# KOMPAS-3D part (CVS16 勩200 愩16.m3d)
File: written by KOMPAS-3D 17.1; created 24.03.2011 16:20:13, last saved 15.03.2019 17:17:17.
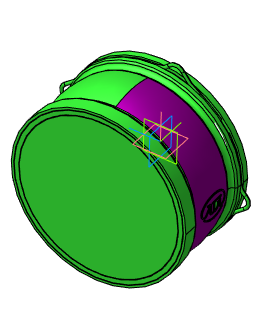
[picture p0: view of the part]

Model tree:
1. Операция без истории:2

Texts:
  Viktor2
